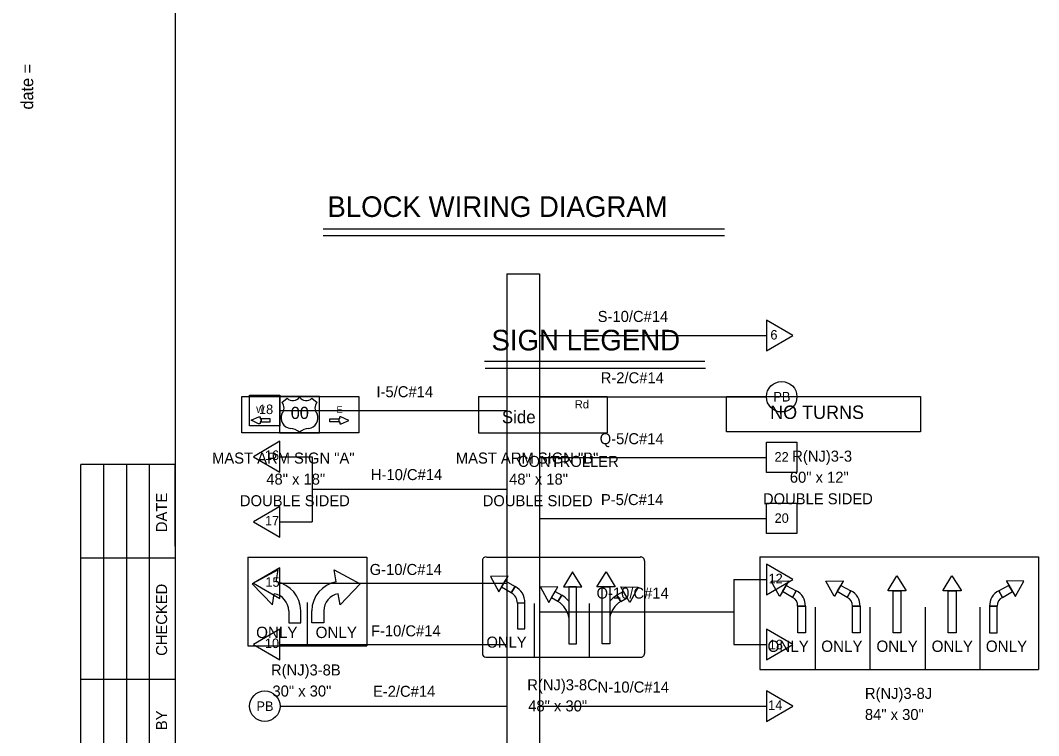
# Model space of a CAD drawing. Extents: x 488740 to 507913, y 466518 to 497949.
# Drawn here: x 507907.771 to 507908.468, y 496046.83 to 496047.319 of the extents above; entities that cross this region are included whole.
import ezdxf

# ---------------------------------------------------------------- set-up
doc = ezdxf.new("R2010")
doc.units = 0
for name, color, linetype in [('1', 7, 'Continuous'), ('25', 7, 'Continuous'), ('38', 7, 'Continuous'), ('9', 7, 'Continuous')]:
    doc.layers.add(name, color=color, linetype=linetype)

msp = doc.modelspace()

# ---------------------------------------------------------------- linework, layer by layer
at = {"layer": '1'}
for p, q in [((507907.8773, 496048.19783), (507907.8773, 496046.44783)), ((507907.8773, 496046.95965), (507907.8773, 496047.01542))]:
    msp.add_line(p, q, dxfattribs=at)
at = {"layer": '25'}
for p, q in [((507907.8773, 496047.01542), (507907.81266, 496047.01542)), ((507907.81266, 496046.44783), (507907.81266, 496047.01542)), ((507907.82841, 496046.44783), (507907.82841, 496047.01542)), ((507907.84416, 496046.44783), (507907.84416, 496047.01542)), ((507907.85958, 496046.44783), (507907.85958, 496047.01542)), ((507907.8773, 496046.95144), (507907.81266, 496046.95144)), ((507907.8773, 496046.86844), (507907.81266, 496046.86844))]:
    msp.add_line(p, q, dxfattribs=at)
at = {"layer": '38'}
for p, q in [((507908.08877, 496047.08605), (507908.23936, 496047.08605)), ((507908.08924, 496047.08136), (507908.23983, 496047.08136)), ((507907.95028, 496047.05797), (507907.95384, 496047.06077)), ((507907.97066, 496047.06077), (507907.97422, 496047.05797)), ((507908.08456, 496047.06202), (507908.08456, 496047.03709)), ((507908.08456, 496047.06202), (507908.17248, 496047.06202)), ((507908.08456, 496047.06202), (507908.17248, 496047.06202)), ((507908.17248, 496047.06202), (507908.17248, 496047.03709)), ((507907.96215, 496047.03705), (507907.96215, 496047.03762)), ((507907.96235, 496047.03762), (507907.96235, 496047.03705)), ((507908.08456, 496047.03709), (507908.17248, 496047.03709)), ((507907.92701, 496046.95214), (507907.92701, 496046.89144)), ((507907.92701, 496046.95214), (507908.00838, 496046.95214)), ((507908.00838, 496046.95214), (507908.00838, 496046.89144)), ((507908.08733, 496046.94988), (507908.08733, 496046.8861)), ((507908.09007, 496046.95214), (507908.19539, 496046.95214)), ((507908.19814, 496046.94955), (507908.19814, 496046.8861)), ((507908.27696, 496046.95217), (507908.46758, 496046.95217)), ((507908.27696, 496046.95217), (507908.27696, 496046.87507)), ((507908.46758, 496046.95217), (507908.46758, 496046.87507)), ((507907.94768, 496046.9433), (507907.92996, 496046.93378)), ((507907.94637, 496046.93509), (507907.94768, 496046.9433)), ((507907.98738, 496046.93509), (507907.98606, 496046.9433)), ((507907.98606, 496046.9433), (507908.00378, 496046.93378)), ((507907.92996, 496046.93378), (507907.94374, 496046.91935)), ((507908.00378, 496046.93378), (507907.99, 496046.91935)), ((507908.10706, 496046.92762), (507908.10961, 496046.93207)), ((507908.29924, 496046.92449), (507908.30185, 496046.92906)), ((507908.33664, 496046.92449), (507908.33925, 496046.92906)), ((507908.44291, 496046.92449), (507908.4403, 496046.92906)), ((507907.94374, 496046.91935), (507907.94502, 496046.927)), ((507907.9677, 496046.89144), (507907.9677, 496046.92097)), ((507907.99, 496046.91935), (507907.98873, 496046.927)), ((507908.11632, 496046.92066), (507908.11119, 496046.92066)), ((507908.12288, 496046.88357), (507908.12288, 496046.92031)), ((507908.13896, 496046.92167), (507908.14151, 496046.92612)), ((507908.14644, 496046.922), (507908.14644, 496046.91066)), ((507908.16061, 496046.88357), (507908.16061, 496046.92031)), ((507908.17437, 496046.922), (507908.17437, 496046.91066)), ((507908.18185, 496046.92167), (507908.17931, 496046.92612)), ((507907.9549, 496046.91541), (507907.9549, 496046.90721)), ((507907.9631, 496046.90721), (507907.9631, 496046.91541)), ((507907.97064, 496046.90721), (507907.97064, 496046.91541)), ((507907.97885, 496046.91541), (507907.97885, 496046.90721)), ((507908.27696, 496046.91346), (507908.27696, 496046.91346)), ((507908.30808, 496046.91856), (507908.30284, 496046.91856)), ((507908.31502, 496046.87507), (507908.31502, 496046.91772)), ((507908.34549, 496046.91856), (507908.34024, 496046.91856)), ((507908.35242, 496046.87507), (507908.35242, 496046.91772)), ((507908.39015, 496046.87507), (507908.39015, 496046.91772)), ((507908.42755, 496046.87507), (507908.42755, 496046.91772)), ((507908.43407, 496046.91856), (507908.43932, 496046.91856)), ((507907.9549, 496046.90721), (507907.9631, 496046.90721)), ((507907.97885, 496046.90721), (507907.97064, 496046.90721)), ((507907.92701, 496046.89144), (507908.00838, 496046.89144)), ((507908.08974, 496046.88357), (507908.19539, 496046.88357)), ((507908.27696, 496046.87507), (507908.46758, 496046.87507))]:
    msp.add_line(p, q, dxfattribs=at)
for points in [[(507907.92281, 496047.06202), (507908.00286, 496047.06202), (507908.00286, 496047.03709), (507907.92281, 496047.03709)], [(507908.25417, 496047.06202), (507908.38672, 496047.06202), (507908.38672, 496047.03774), (507908.25417, 496047.03774)], [(507907.93589, 496047.04474), (507907.93584, 496047.04474), (507907.93567, 496047.04474), (507907.93556, 496047.04468), (507907.93539, 496047.04463), (507907.93533, 496047.04457), (507907.93533, 496047.04451), (507907.93528, 496047.04356), (507907.93528, 496047.0435), (507907.93522, 496047.04344), (507907.93516, 496047.04339), (507907.93505, 496047.04333), (507907.93499, 496047.04333), (507907.93488, 496047.04322), (507907.93471, 496047.04322), (507907.93454, 496047.04322), (507907.93432, 496047.04333), (507907.92914, 496047.04569), (507907.93449, 496047.04806), (507907.93454, 496047.04811), (507907.93471, 496047.04817), (507907.93488, 496047.04817), (507907.93505, 496047.04811), (507907.93516, 496047.04806), (507907.93528, 496047.048), (507907.93533, 496047.04789), (507907.93539, 496047.04783), (507907.93539, 496047.04693), (507907.93539, 496047.04682), (507907.93539, 496047.04676), (507907.9355, 496047.04671), (507907.9355, 496047.04671), (507907.93556, 496047.04665), (507907.93567, 496047.04665), (507907.93567, 496047.04665), (507907.93595, 496047.04665)], [(507907.93595, 496047.04474), (507907.94214, 496047.04474), (507907.94214, 496047.04665), (507907.93595, 496047.04665)], [(507907.98914, 496047.0447), (507907.98295, 496047.0447), (507907.98295, 496047.04661), (507907.98914, 496047.04661)], [(507907.98919, 496047.0447), (507907.98925, 496047.0447), (507907.98942, 496047.0447), (507907.98953, 496047.04464), (507907.9897, 496047.04459), (507907.98976, 496047.04453), (507907.98976, 496047.04447), (507907.98981, 496047.04352), (507907.98981, 496047.04346), (507907.98987, 496047.04341), (507907.98992, 496047.04335), (507907.99004, 496047.04329), (507907.99009, 496047.04329), (507907.99021, 496047.04318), (507907.99037, 496047.04318), (507907.99054, 496047.04318), (507907.99077, 496047.04329), (507907.99594, 496047.04566), (507907.9906, 496047.04802), (507907.99054, 496047.04807), (507907.99037, 496047.04813), (507907.99021, 496047.04813), (507907.99004, 496047.04807), (507907.98992, 496047.04802), (507907.98981, 496047.04796), (507907.98976, 496047.04785), (507907.9897, 496047.04779), (507907.9897, 496047.04689), (507907.9897, 496047.04678), (507907.9897, 496047.04672), (507907.98959, 496047.04667), (507907.98959, 496047.04667), (507907.98953, 496047.04661), (507907.98942, 496047.04661), (507907.98942, 496047.04661), (507907.98914, 496047.04661)], [(507908.14892, 496046.94198), (507908.14277, 496046.93177), (507908.15525, 496046.93176)], [(507908.17189, 496046.94198), (507908.17804, 496046.93177), (507908.16557, 496046.93176)], [(507908.09282, 496046.9387), (507908.09855, 496046.92825), (507908.10484, 496046.93903)], [(507908.10042, 496046.93141), (507908.10297, 496046.93586), (507908.10961, 496046.93207), (507908.10706, 496046.92762)], [(507908.2907, 496046.92545), (507908.29037, 496046.92545), (507908.28479, 496046.93562), (507908.2966, 496046.93595), (507908.2966, 496046.93562)], [(507908.3281, 496046.92545), (507908.32777, 496046.92545), (507908.32219, 496046.93562), (507908.334, 496046.93595), (507908.334, 496046.93562)], [(507908.36469, 496046.92906), (507908.36469, 496046.92938), (507908.37059, 496046.93923), (507908.37683, 496046.92938), (507908.37683, 496046.92906)], [(507908.4024, 496046.92906), (507908.4024, 496046.92938), (507908.40831, 496046.93923), (507908.41454, 496046.92938), (507908.41454, 496046.92906)], [(507908.45146, 496046.92545), (507908.45179, 496046.92545), (507908.45736, 496046.93562), (507908.44555, 496046.93595), (507908.44555, 496046.93562)], [(507908.12694, 496046.93148), (507908.13267, 496046.92103), (507908.13896, 496046.93181)], [(507908.13454, 496046.92419), (507908.13709, 496046.92865), (507908.14151, 496046.92612), (507908.13896, 496046.92167)], [(507908.14644, 496046.89277), (507908.15157, 496046.89277), (507908.15157, 496046.93177), (507908.14644, 496046.93177)], [(507908.17437, 496046.89277), (507908.16924, 496046.89277), (507908.16924, 496046.93177), (507908.17437, 496046.93177)], [(507908.18627, 496046.92419), (507908.18373, 496046.92865), (507908.17931, 496046.92612), (507908.18185, 496046.92167)], [(507908.19387, 496046.93148), (507908.18814, 496046.92103), (507908.18185, 496046.93181)], [(507908.29492, 496046.93271), (507908.30185, 496046.92906), (507908.29923, 496046.92446), (507908.29248, 496046.92848)], [(507908.33232, 496046.93271), (507908.33925, 496046.92906), (507908.33663, 496046.92446), (507908.32988, 496046.92848)], [(507908.37339, 496046.90019), (507908.36812, 496046.90019), (507908.36812, 496046.92906), (507908.37339, 496046.92906)], [(507908.4111, 496046.90019), (507908.40584, 496046.90019), (507908.40584, 496046.92906), (507908.4111, 496046.92906)], [(507908.44723, 496046.93271), (507908.4403, 496046.92906), (507908.44293, 496046.92446), (507908.44968, 496046.92848)], [(507908.11119, 496046.90294), (507908.11632, 496046.90294), (507908.11632, 496046.92066), (507908.11119, 496046.92066)], [(507908.30808, 496046.90019), (507908.30284, 496046.90019), (507908.30284, 496046.91856), (507908.30808, 496046.91856)], [(507908.34549, 496046.90019), (507908.34024, 496046.90019), (507908.34024, 496046.91856), (507908.34549, 496046.91856)], [(507908.43407, 496046.90019), (507908.43932, 496046.90019), (507908.43932, 496046.91856), (507908.43407, 496046.91856)]]:
    msp.add_lwpolyline(points, close=True, dxfattribs=at)
msp.add_lwpolyline([(507907.96235, 496047.03705), (507907.97603, 496047.03705), (507907.97603, 496047.06198), (507907.94847, 496047.06198), (507907.94847, 496047.03705), (507907.96215, 496047.03705)], dxfattribs=at)
for centre, radius, start, end in [((507907.95769, 496047.06478), 0.00557, 226.13784, 324.97605), ((507907.96681, 496047.06478), 0.00557, 215.02395, 313.86216), ((507907.94582, 496047.05409), 0.00591, 318.96758, 41.03242), ((507907.97868, 496047.05409), 0.00591, 138.96758, 221.03243), ((507907.9569, 496047.04727), 0.00724, 156.10933, 263.19699), ((507907.9676, 496047.04727), 0.00724, 276.80301, 23.89067), ((507907.95514, 496047.02907), 0.01105, 50.63578, 85.32525), ((507907.96936, 496047.02907), 0.01105, 94.67475, 129.36423), ((507908.08973, 496046.94978), 0.00241, 84.73874, 177.63311), ((507908.19546, 496046.9495), 0.00268, 1.08904, 93.98033), ((507907.94289, 496046.91519), 0.02021, 0.63274, 80.09634), ((507907.99085, 496046.91519), 0.02021, 99.90366, 179.36726), ((507908.10353, 496046.92081), 0.00767, 358.83551, 62.52682), ((507908.10378, 496046.92096), 0.01255, 358.62032, 62.31163), ((507908.29661, 496046.91884), 0.01148, 358.57482, 62.82463), ((507908.33401, 496046.91884), 0.01148, 358.57482, 62.82463), ((507908.44555, 496046.91884), 0.01148, 117.17537, 181.42518), ((507907.94289, 496046.91519), 0.01201, 0.63274, 79.7949), ((507907.99085, 496046.91519), 0.01201, 100.2051, 179.36726), ((507908.13057, 496046.90792), 0.01611, 9.7849, 58.59208), ((507908.13043, 496046.90783), 0.02138, 41.49862, 58.79284), ((507908.19038, 496046.90783), 0.02138, 121.20716, 138.50138), ((507908.19024, 496046.90792), 0.01611, 121.40792, 170.2151), ((507908.29661, 496046.91884), 0.00623, 357.37479, 64.99082), ((507908.33401, 496046.91884), 0.00623, 357.37479, 64.99082), ((507908.44555, 496046.91884), 0.00623, 115.00918, 182.62521), ((507908.08967, 496046.88594), 0.00234, 176.13508, 269.02944), ((507908.19548, 496046.88625), 0.00266, 265.44951, 356.72662)]:
    msp.add_arc(centre, radius, start, end, dxfattribs=at)
at = {"layer": '9'}
for p, q in [((507907.97847, 496047.17673), (507908.25279, 496047.17673)), ((507907.97847, 496047.17218), (507908.25279, 496047.17218)), ((507908.104, 496047.1458), (507908.104, 496046.55381)), ((507908.104, 496047.1458), (507908.12631, 496047.1458)), ((507908.12631, 496047.1458), (507908.12631, 496046.55381)), ((507908.12631, 496047.1038), (507908.2815, 496047.1038)), ((507907.92815, 496047.06279), (507907.94882, 496047.06279)), ((507907.92815, 496047.0418), (507907.92815, 496047.06279)), ((507907.94882, 496047.06279), (507907.94882, 496047.0418)), ((507908.12631, 496047.06181), (507908.2815, 496047.06181)), ((507907.94882, 496047.05229), (507908.104, 496047.05229)), ((507907.94882, 496047.0418), (507907.92815, 496047.0418)), ((507908.2815, 496047.03064), (507908.30217, 496047.03064)), ((507908.2815, 496047.00997), (507908.2815, 496047.03064)), ((507908.30217, 496047.03064), (507908.30217, 496047.00997)), ((507907.94882, 496047.0208), (507907.9708, 496047.0208)), ((507907.9708, 496047.0208), (507907.9708, 496046.97618)), ((507908.12631, 496047.02014), (507908.2815, 496047.02014)), ((507908.30217, 496047.00997), (507908.2815, 496047.00997)), ((507907.9708, 496046.99849), (507908.104, 496046.99849)), ((507908.2815, 496046.98897), (507908.30217, 496046.98897)), ((507908.2815, 496046.9683), (507908.2815, 496046.98897)), ((507908.30217, 496046.98897), (507908.30217, 496046.9683)), ((507907.94882, 496046.97618), (507907.9708, 496046.97618)), ((507908.12631, 496046.97847), (507908.2815, 496046.97847)), ((507908.30217, 496046.9683), (507908.2815, 496046.9683)), ((507907.94882, 496046.93418), (507908.104, 496046.93418)), ((507908.25919, 496046.93681), (507908.25919, 496046.89219)), ((507908.25919, 496046.93681), (507908.2815, 496046.93681)), ((507908.25919, 496046.9145), (507908.12631, 496046.9145)), ((507907.94882, 496046.89219), (507908.104, 496046.89219)), ((507908.25919, 496046.89219), (507908.2815, 496046.89219)), ((507907.94882, 496046.85019), (507908.104, 496046.85019)), ((507908.12631, 496046.85019), (507908.2815, 496046.85019))]:
    msp.add_line(p, q, dxfattribs=at)
for points in [[(507908.2815, 496047.0933), (507908.29954, 496047.1038), (507908.2815, 496047.1143), (507908.2815, 496047.0933)], [(507907.94882, 496047.0313), (507907.93077, 496047.0208), (507907.94882, 496047.0103), (507907.94882, 496047.0313)], [(507907.94882, 496046.98668), (507907.93077, 496046.97618), (507907.94882, 496046.96568), (507907.94882, 496046.98668)], [(507907.94882, 496046.94468), (507907.93077, 496046.93418), (507907.94882, 496046.92368), (507907.94882, 496046.94468)], [(507908.2815, 496046.92631), (507908.29954, 496046.93681), (507908.2815, 496046.94731), (507908.2815, 496046.92631)], [(507907.94882, 496046.90269), (507907.93077, 496046.89219), (507907.94882, 496046.88169), (507907.94882, 496046.90269)], [(507908.2815, 496046.88169), (507908.29954, 496046.89219), (507908.2815, 496046.90269), (507908.2815, 496046.88169)], [(507908.2815, 496046.8397), (507908.29954, 496046.85019), (507908.2815, 496046.86069), (507908.2815, 496046.8397)]]:
    msp.add_lwpolyline(points, dxfattribs=at)
for centre in [(507908.29193, 496047.06181), (507907.93852, 496046.85006)]:
    msp.add_circle(centre, 0.01043, dxfattribs=at)

# ---------------------------------------------------------------- texts
at = {"layer": '1'}
for s, height, p in [('.......time......', 0.0001201, (507907.78018, 496047.31506)), ('date =', 0.008335, (507907.78018, 496047.2583))]:
    msp.add_text(s, height=height, rotation=90, dxfattribs=at).set_placement(p)
at = {"layer": '25'}
for s, p in [('DATE', (507907.87172, 496046.96916)), ('CHECKED', (507907.87172, 496046.88451)), ('BY', (507907.87172, 496046.83366))]:
    msp.add_text(s, height=0.007545, rotation=90, dxfattribs=at).set_placement(p)
at = {"layer": '38'}
for s, height, p in [('SIGN LEGEND', 0.0141083, (507908.0935, 496047.0935)), ('Rd', 0.005634, (507908.1505, 496047.05382)), ('W', 0.00468, (507907.93256, 496047.05063)), ('00', 0.008313, (507907.95627, 496047.0466)), ('E', 0.00468, (507907.98757, 496047.05059)), ('Side', 0.008624, (507908.10063, 496047.04365)), ('NO TURNS', 0.009187, (507908.28403, 496047.0466)), ('R(NJ)3-3', 0.007545, (507908.29912, 496047.0174)), ('MAST ARM SIGN "A"', 0.0075453, (507907.90247, 496047.01609)), ('MAST ARM SIGN "B"', 0.0075453, (507908.06914, 496047.01609)), ('48" x 18"', 0.007545, (507907.93954, 496047.00166)), ('48" x 18"', 0.007545, (507908.10555, 496047.00166)), ('60" x 12"', 0.007545, (507908.29748, 496047.00297)), ('DOUBLE SIDED', 0.0075453, (507907.9215, 496046.98689)), ('DOUBLE SIDED', 0.0075453, (507908.08751, 496046.98689)), ('DOUBLE SIDED', 0.0075453, (507908.27911, 496046.9882)), ('ONLY', 0.007762, (507907.93259, 496046.89669)), ('ONLY', 0.007762, (507907.97327, 496046.89669)), ('ONLY', 0.007545, (507908.09007, 496046.89013)), ('ONLY', 0.007762, (507908.28221, 496046.88721)), ('ONLY', 0.007762, (507908.31896, 496046.88721)), ('ONLY', 0.007762, (507908.35669, 496046.88721)), ('ONLY', 0.007762, (507908.39442, 496046.88721)), ('ONLY', 0.007762, (507908.43149, 496046.88721)), ('R(NJ)3-8B', 0.007545, (507907.94276, 496046.8711)), ('R(NJ)3-8C', 0.007545, (507908.11796, 496046.86093)), ('30" x 30"', 0.007545, (507907.94375, 496046.85667)), ('R(NJ)3-8J', 0.007545, (507908.34881, 496046.85506)), ('48" x 30"', 0.007545, (507908.11861, 496046.8465)), ('84" x 30"', 0.007545, (507908.34881, 496046.84062))]:
    msp.add_text(s, height=height, dxfattribs=at).set_placement(p)
at = {"layer": '9'}
for s, height, p in [('BLOCK WIRING DIAGRAM', 0.0141083, (507907.9813, 496047.18484)), ('S-10/C#14', 0.007545, (507908.16611, 496047.11299)), ('6', 0.00651, (507908.28419, 496047.10096)), ('R-2/C#14', 0.007545, (507908.16818, 496047.07099)), ('I-5/C#14', 0.007545, (507908.01486, 496047.06148)), ('PB', 0.00651, (507908.28625, 496047.05855)), ('18', 0.00651, (507907.93456, 496047.04995)), ('Q-5/C#14', 0.007545, (507908.16749, 496047.02933)), ('16', 0.00651, (507907.93861, 496047.01856)), ('CONTROLLER', 0.007545, (507908.11155, 496047.01378)), ('22', 0.00651, (507908.28702, 496047.0174)), ('H-10/C#14', 0.007545, (507908.01104, 496047.00477)), ('P-5/C#14', 0.007545, (507908.16834, 496046.98766)), ('17', 0.00651, (507907.93864, 496046.97372)), ('20', 0.00651, (507908.28707, 496046.97552)), ('G-10/C#14', 0.007545, (507908.01023, 496046.93985)), ('15', 0.00651, (507907.93893, 496046.93177)), ('12', 0.00651, (507908.28294, 496046.93422)), ('O-10/C#14', 0.007545, (507908.16533, 496046.92368)), ('F-10/C#14', 0.007545, (507908.0111, 496046.89785)), ('10', 0.00651, (507907.93861, 496046.88983)), ('13', 0.00651, (507908.28312, 496046.88903)), ('N-10/C#14', 0.007545, (507908.16606, 496046.85938)), ('E-2/C#14', 0.007545, (507908.01247, 496046.85648)), ('PB', 0.00651, (507907.93283, 496046.8468)), ('14', 0.00651, (507908.28264, 496046.84753))]:
    msp.add_text(s, height=height, dxfattribs=at).set_placement(p)

doc.saveas('drawing.dxf')
